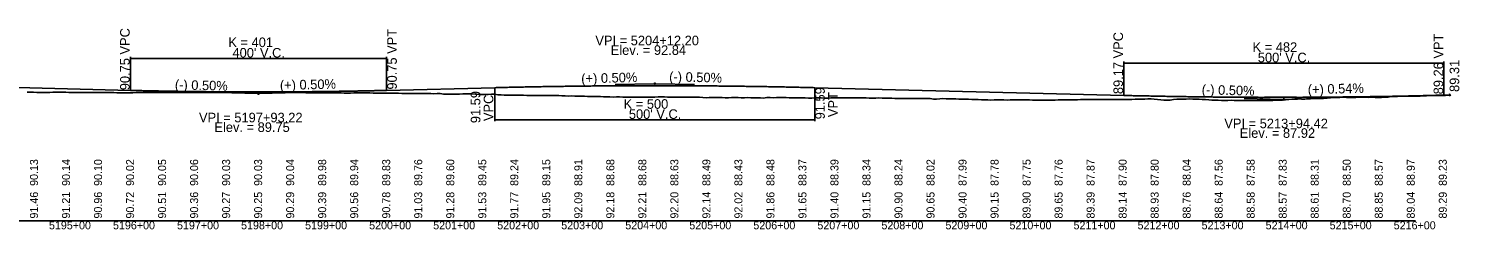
# Model space of a CAD drawing. Extents: x 2121671 to 2169879, y 557274 to 599957.
# Drawn here: x 2149002 to 2151237, y 576173 to 576487 of the extents above; entities that cross this region are included whole.
import ezdxf

# ---------------------------------------------------------------- set-up
doc = ezdxf.new("R2010")
doc.units = 0
for name, color, linetype in [('RD_DDB_GradeTX', 7, 'Continuous'), ('RD_DDB_Profile_EX', 7, 'Continuous'), ('RD_DDB_Profile_Lbl', 7, 'Continuous'), ('RD_DDB_Profile_PR', 7, 'Continuous'), ('RD_DDB_StaTX', 7, 'Continuous'), ('RD_DDB_StripGrade', 7, 'Continuous'), ('RD_DDB_VCLbl', 7, 'Continuous'), ('RD_GPK_Profile_Cell', 7, 'Continuous')]:
    doc.layers.add(name, color=color, linetype=linetype)

msp = doc.modelspace()

# ---------------------------------------------------------------- linework, layer by layer
at = {"layer": 'RD_DDB_GradeTX'}
for p, q in [((2149918.1, 576399.5), (2149979.1, 576401)), ((2150042.1, 576399.5), (2149981.1, 576401)), ((2149299.2, 576387.1), (2149360.1, 576385.6)), ((2149423.1, 576387.1), (2149362.1, 576385.6)), ((2150900.4, 576378), (2150961.3, 576376.5)), ((2151024.3, 576378.1), (2150963.3, 576376.5))]:
    msp.add_line(p, q, dxfattribs=at)
for centre in [(2149980.1, 576401), (2149361.1, 576385.6), (2150962.3, 576376.4), (2151221.5, 576383.4)]:
    msp.add_circle(centre, 1, dxfattribs=at)
at = {"layer": 'RD_DDB_Profile_EX'}
for points in [[(2149000.1, 576387.7), (2149005.1, 576387.7), (2149010.1, 576387.6), (2149015.1, 576387.5), (2149020.1, 576387.5), (2149025.1, 576387.5), (2149030.1, 576387.5), (2149035.1, 576387.5), (2149040.1, 576387.6), (2149045.1, 576387.6), (2149050.1, 576387.7), (2149055.1, 576387.6), (2149060.1, 576387.6), (2149065.1, 576387.5), (2149070.1, 576387.5), (2149075.1, 576387.5), (2149080.1, 576387.5), (2149085.1, 576387.4), (2149090.1, 576387.4), (2149095.1, 576387.4), (2149100.1, 576387.4), (2149105.1, 576387.4), (2149110.1, 576387.4), (2149115.1, 576387.3), (2149120.1, 576387.3), (2149125.1, 576387.3), (2149130.1, 576387.1), (2149135.1, 576387), (2149140.1, 576386.9), (2149145.1, 576386.8), (2149150.1, 576386.9), (2149155.1, 576386.9), (2149160.1, 576386.9), (2149165.1, 576386.9), (2149170.1, 576387), (2149175.1, 576387), (2149180.1, 576387), (2149185.1, 576387), (2149190.1, 576387), (2149195.1, 576387), (2149200.1, 576387), (2149205.1, 576387), (2149210.1, 576387), (2149215.1, 576387), (2149220.1, 576387.1), (2149225.1, 576387.1)], [(2149225.1, 576387.1), (2149230.1, 576387.2), (2149235.1, 576387.2), (2149240.1, 576387.3), (2149245.1, 576387.3), (2149250.1, 576387.2), (2149255.1, 576387.2), (2149260.1, 576387.2), (2149265.1, 576387.2), (2149270.1, 576387.1), (2149275.1, 576387.1), (2149280.1, 576387.1), (2149285.1, 576387.1), (2149290.1, 576387), (2149295.1, 576387), (2149300.1, 576387), (2149305.1, 576387), (2149310.1, 576387), (2149315.1, 576387), (2149320.1, 576387), (2149325.1, 576387), (2149330.1, 576387), (2149335.1, 576387), (2149340.1, 576387), (2149345.1, 576387), (2149350.1, 576387), (2149355.1, 576387), (2149360.1, 576387), (2149365.1, 576387), (2149370.1, 576387), (2149375.1, 576386.9), (2149380.1, 576386.9), (2149385.1, 576386.9), (2149390.1, 576386.9), (2149395.1, 576386.9), (2149400.1, 576387), (2149405.1, 576387), (2149410.1, 576387), (2149415.1, 576387.1), (2149420.1, 576387), (2149425.1, 576387), (2149430.1, 576387), (2149435.1, 576386.9), (2149440.1, 576386.8), (2149445.1, 576386.8), (2149450.1, 576386.7), (2149455.1, 576386.7), (2149460.1, 576386.7), (2149465.1, 576386.7), (2149470.1, 576386.8), (2149475.1, 576386.8), (2149480.1, 576386.6), (2149485.1, 576386.6), (2149490.1, 576386.5), (2149495.1, 576386.4), (2149500.1, 576386.4), (2149505.1, 576386.3), (2149510.1, 576386.5), (2149515.1, 576386.5), (2149520.1, 576386.5), (2149525.1, 576386.5), (2149530.1, 576386.5), (2149535.1, 576386.5), (2149540.1, 576386.4), (2149545.1, 576386.4), (2149550.1, 576386.3), (2149555.1, 576386.2), (2149560.1, 576386.1), (2149565.1, 576386), (2149570.1, 576386), (2149575.1, 576386), (2149580.1, 576386), (2149585.1, 576385.9), (2149590.1, 576385.9), (2149595.1, 576385.9), (2149600.1, 576385.8), (2149605.1, 576385.8), (2149610.1, 576385.8), (2149615.1, 576385.7), (2149620.1, 576385.6), (2149625.1, 576385.5), (2149630.1, 576385.5), (2149635.1, 576385.4), (2149640.1, 576385.5), (2149645.1, 576385.5), (2149650.1, 576384.9), (2149655.1, 576384.8), (2149660.1, 576384.8), (2149665.1, 576384.8), (2149670.1, 576384.8), (2149675.1, 576384.9), (2149680.1, 576385.2), (2149685.1, 576385.3), (2149690.1, 576385.2), (2149695.1, 576385.1), (2149700.1, 576384.9), (2149705.1, 576384.1), (2149710.1, 576384.1), (2149715.1, 576384), (2149720.1, 576384.1), (2149725.1, 576384.9)], [(2149725.1, 576384.9), (2149730.1, 576384.7), (2149735.1, 576383.7), (2149740.1, 576383.4), (2149745.1, 576383.3), (2149750.1, 576383.2), (2149755.1, 576383.1), (2149760.1, 576383.1), (2149765.1, 576383), (2149770.1, 576383), (2149775.1, 576382.9), (2149780.1, 576382.8), (2149785.1, 576382.7), (2149790.1, 576382.6), (2149795.1, 576382.5), (2149800.1, 576382.6), (2149805.1, 576382.6), (2149810.1, 576382.6), (2149815.1, 576382.6), (2149820.1, 576382.6), (2149825.1, 576382.6), (2149830.1, 576382.5), (2149835.1, 576382.1), (2149840.1, 576381.9), (2149845.1, 576381.6), (2149850.1, 576381.8), (2149855.1, 576381.6), (2149860.1, 576381.5), (2149865.1, 576381.4), (2149870.1, 576381.4), (2149875.1, 576381.1), (2149880.1, 576381), (2149885.1, 576381), (2149890.1, 576381.1), (2149895.1, 576381.1), (2149900.1, 576380.7), (2149905.1, 576380.4), (2149910.1, 576380.3), (2149915.1, 576380.1), (2149920.1, 576380.3), (2149925.1, 576380.3), (2149930.1, 576380), (2149935.1, 576379.7), (2149940.1, 576379.8), (2149945.1, 576379.9), (2149950.1, 576379.9), (2149955.1, 576379.9), (2149960.1, 576380.1), (2149965.1, 576380.2), (2149970.1, 576380.2), (2149975.1, 576380.1), (2149980.1, 576380.2), (2149985.1, 576380.3), (2149990.1, 576380.4), (2149995.1, 576380.3), (2150000.1, 576380.2), (2150005.1, 576380.2), (2150010.1, 576380.2), (2150015.1, 576380.1), (2150020.1, 576379.9), (2150025.1, 576379.8), (2150030.1, 576379.7), (2150035.1, 576379.8), (2150040.1, 576379.9), (2150045.1, 576379.9), (2150050.1, 576379.8), (2150055.1, 576379.3), (2150060.1, 576379.1), (2150065.1, 576379.2), (2150070.1, 576379.4), (2150075.1, 576379.4), (2150080.1, 576379.3), (2150085.1, 576379.2), (2150090.1, 576379), (2150095.1, 576379.1), (2150100.1, 576379.3), (2150105.1, 576379.3), (2150110.1, 576379.2), (2150115.1, 576378.9), (2150120.1, 576379), (2150125.1, 576379.2), (2150130.1, 576379), (2150135.1, 576378.8), (2150140.1, 576379), (2150145.1, 576378.7), (2150150.1, 576378.6), (2150155.1, 576379.3), (2150160.1, 576379.4), (2150165.1, 576379.1), (2150170.1, 576379.3), (2150175.1, 576379.3), (2150180.1, 576379.4), (2150185.1, 576379.4), (2150190.1, 576378.9), (2150195.1, 576378.7), (2150200.1, 576378.8), (2150205.1, 576378.9), (2150210.1, 576378.9), (2150215.1, 576378.7), (2150220.1, 576378.6), (2150225.1, 576378.5)], [(2150225.1, 576378.5), (2150230.1, 576378.9), (2150235.1, 576378.8), (2150240.1, 576378.9), (2150245.1, 576378.6), (2150250.1, 576378.6), (2150255.1, 576378.8), (2150260.1, 576378.7), (2150265.1, 576378.7), (2150270.1, 576378.8), (2150275.1, 576379), (2150280.1, 576378.8), (2150285.1, 576378.7), (2150290.1, 576378.7), (2150295.1, 576378.8), (2150300.1, 576378.8), (2150305.1, 576378.8), (2150310.1, 576378.7), (2150315.1, 576378.4), (2150320.1, 576378.6), (2150325.1, 576378.4), (2150330.1, 576378.7), (2150335.1, 576378.6), (2150340.1, 576378.6), (2150345.1, 576378.6), (2150350.1, 576378.3), (2150355.1, 576377.9), (2150360.1, 576378), (2150365.1, 576377.9), (2150370.1, 576378.1), (2150375.1, 576377.9), (2150380.1, 576378), (2150385.1, 576378.1), (2150390.1, 576378), (2150395.1, 576378), (2150400.1, 576377.8), (2150405.1, 576377.9), (2150410.1, 576377.9), (2150415.1, 576376.9), (2150420.1, 576376.9), (2150425.1, 576377.6), (2150430.1, 576377.7), (2150435.1, 576377.6), (2150440.1, 576377.5), (2150445.1, 576377.5), (2150450.1, 576377.3), (2150455.1, 576377), (2150460.1, 576377), (2150465.1, 576376.9), (2150470.1, 576376.7), (2150475.1, 576376.4), (2150480.1, 576376.2), (2150485.1, 576376.1), (2150490.1, 576376), (2150495.1, 576375.9), (2150500.1, 576375.7), (2150505.1, 576375.5), (2150510.1, 576375.7), (2150515.1, 576375.7), (2150520.1, 576375.7), (2150525.1, 576375.6), (2150530.1, 576375.5), (2150535.1, 576375.7), (2150540.1, 576375.9), (2150545.1, 576376), (2150550.1, 576375.9), (2150555.1, 576375.8), (2150560.1, 576375.7), (2150565.1, 576375.6), (2150570.1, 576375.5), (2150575.1, 576375.5), (2150580.1, 576375.5), (2150585.1, 576375.5), (2150590.1, 576375.5), (2150595.1, 576375.5), (2150600.1, 576375.5), (2150605.1, 576375.5), (2150610.1, 576375.6), (2150615.1, 576375.6), (2150620.1, 576375.7), (2150625.1, 576375.7), (2150630.1, 576375.8), (2150635.1, 576375.9), (2150640.1, 576376), (2150645.1, 576376.1), (2150650.1, 576376.1), (2150655.1, 576376.3), (2150660.1, 576376.3), (2150665.1, 576376.2), (2150670.1, 576376.2), (2150675.1, 576376.1), (2150680.1, 576376.3), (2150685.1, 576376.3), (2150690.1, 576376.2), (2150695.1, 576376.3), (2150700.1, 576376.3), (2150705.1, 576376.3), (2150710.1, 576376.3), (2150715.1, 576376.3), (2150720.1, 576376.3), (2150725.1, 576376.3)], [(2150725.1, 576376.3), (2150730.1, 576376.6), (2150735.1, 576376.8), (2150740.1, 576376.8), (2150745.1, 576376.9), (2150750.1, 576377.1), (2150755.1, 576377.2), (2150760.1, 576376.9), (2150765.1, 576376.1), (2150770.1, 576375.6), (2150775.1, 576375.3), (2150780.1, 576375.1), (2150785.1, 576375.4), (2150790.1, 576376.1), (2150795.1, 576376.6), (2150800.1, 576376.9), (2150805.1, 576376.9), (2150810.1, 576377), (2150815.1, 576377.1), (2150820.1, 576376.9), (2150825.1, 576376.9), (2150830.1, 576376.9), (2150835.1, 576376.5), (2150840.1, 576376.1), (2150845.1, 576375.6), (2150850.1, 576375.3), (2150855.1, 576375.2), (2150860.1, 576375.1), (2150865.1, 576374.7), (2150870.1, 576374.6), (2150875.1, 576375), (2150880.1, 576375.3), (2150885.1, 576374.7), (2150890.1, 576374.6), (2150895.1, 576374.5), (2150900.1, 576374.6), (2150905.1, 576374.6), (2150910.1, 576374.7), (2150915.1, 576374.8), (2150920.1, 576374.7), (2150925.1, 576374.7), (2150930.1, 576374.7), (2150935.1, 576374.7), (2150940.1, 576374.9), (2150945.1, 576375), (2150950.1, 576375.1), (2150955.1, 576375.1), (2150960.1, 576375.4), (2150965.1, 576375.6), (2150970.1, 576376.2), (2150975.1, 576376.6), (2150980.1, 576377.5), (2150985.1, 576377.1), (2150990.1, 576376.7), (2150995.1, 576376.8), (2151000.1, 576377.7), (2151005.1, 576378), (2151010.1, 576378.2), (2151015.1, 576378.4), (2151020.1, 576378.4), (2151025.1, 576378.4), (2151030.1, 576378.6), (2151035.1, 576379.1), (2151040.1, 576379.5), (2151045.1, 576379.5), (2151050.1, 576379.4), (2151055.1, 576379.9), (2151060.1, 576379.4), (2151065.1, 576379.4), (2151070.1, 576379.3), (2151075.1, 576379.3), (2151080.1, 576379.8), (2151085.1, 576380), (2151090.1, 576380), (2151095.1, 576379.5), (2151100.1, 576380), (2151105.1, 576379.5), (2151110.1, 576379.6), (2151115.1, 576379.5), (2151120.1, 576379.8), (2151125.1, 576380.2), (2151130.1, 576380.8), (2151135.1, 576381.1), (2151140.1, 576381.2), (2151145.1, 576381.3), (2151150.1, 576381.3), (2151155.1, 576381.4), (2151160.1, 576381.6), (2151165.1, 576381.6), (2151170.1, 576381.7), (2151175.1, 576381.7), (2151180.1, 576382.1), (2151185.1, 576382.3), (2151190.1, 576382.6), (2151195.1, 576382.6), (2151200.1, 576382.5), (2151205.1, 576382.4), (2151210.1, 576382.6), (2151215.1, 576382.7), (2151220.1, 576383.2), (2151221.5, 576383.2)]]:
    msp.add_lwpolyline(points, dxfattribs=at)
at = {"layer": 'RD_DDB_Profile_PR'}
for p, q in [((2148964.4, 576395.5), (2149161.1, 576390.6)), ((2149561.1, 576390.6), (2149730.1, 576394.8)), ((2150230.1, 576394.8), (2150712.3, 576382.7)), ((2151212.3, 576383.1), (2151221.5, 576383.4))]:
    msp.add_line(p, q, dxfattribs=at)
for points in [[(2149730.1, 576394.8), (2149740.1, 576395), (2149750.1, 576395.3), (2149760.1, 576395.5), (2149770.1, 576395.7), (2149780.1, 576395.9), (2149790.1, 576396.1), (2149800.1, 576396.3), (2149810.1, 576396.5), (2149820.1, 576396.6), (2149830.1, 576396.8), (2149840.1, 576396.9), (2149850.1, 576397.1), (2149860.1, 576397.2), (2149870.1, 576397.3), (2149880.1, 576397.4), (2149890.1, 576397.5), (2149900.1, 576397.6), (2149910.1, 576397.7), (2149920.1, 576397.7), (2149930.1, 576397.8), (2149940.1, 576397.8), (2149950.1, 576397.9), (2149960.1, 576397.9), (2149970.1, 576397.9), (2149980.1, 576397.9), (2149990.1, 576397.9), (2150000.1, 576397.9), (2150010.1, 576397.9), (2150020.1, 576397.8), (2150030.1, 576397.8), (2150040.1, 576397.7), (2150050.1, 576397.7), (2150060.1, 576397.6), (2150070.1, 576397.5), (2150080.1, 576397.4), (2150090.1, 576397.3), (2150100.1, 576397.2), (2150110.1, 576397.1), (2150120.1, 576396.9), (2150130.1, 576396.8), (2150140.1, 576396.6), (2150150.1, 576396.5), (2150160.1, 576396.3), (2150170.1, 576396.1), (2150180.1, 576395.9), (2150190.1, 576395.7), (2150200.1, 576395.5), (2150210.1, 576395.2), (2150220.1, 576395), (2150230.1, 576394.8)], [(2149161.1, 576390.6), (2149169.1, 576390.4), (2149177.1, 576390.2), (2149185.1, 576390), (2149193.1, 576389.8), (2149201.1, 576389.7), (2149209.1, 576389.5), (2149217.1, 576389.4), (2149225.1, 576389.2), (2149233.1, 576389.1), (2149241.1, 576389), (2149249.1, 576388.9), (2149257.1, 576388.7), (2149265.1, 576388.6), (2149273.1, 576388.6), (2149281.1, 576388.5), (2149289.1, 576388.4), (2149297.1, 576388.3), (2149305.1, 576388.3), (2149313.1, 576388.2), (2149321.1, 576388.2), (2149329.1, 576388.1), (2149337.1, 576388.1), (2149345.1, 576388.1), (2149353.1, 576388.1), (2149361.1, 576388.1), (2149369.1, 576388.1), (2149377.1, 576388.1), (2149385.1, 576388.1), (2149393.1, 576388.1), (2149401.1, 576388.2), (2149409.1, 576388.2), (2149417.1, 576388.3), (2149425.1, 576388.3), (2149433.1, 576388.4), (2149441.1, 576388.5), (2149449.1, 576388.6), (2149457.1, 576388.6), (2149465.1, 576388.7), (2149473.1, 576388.9), (2149481.1, 576389), (2149489.1, 576389.1), (2149497.1, 576389.2), (2149505.1, 576389.4), (2149513.1, 576389.5), (2149521.1, 576389.7), (2149529.1, 576389.8), (2149537.1, 576390), (2149545.1, 576390.2), (2149553.1, 576390.4), (2149561.1, 576390.6)], [(2150712.3, 576382.7), (2150722.3, 576382.4), (2150732.3, 576382.2), (2150742.3, 576382), (2150752.3, 576381.8), (2150762.3, 576381.6), (2150772.3, 576381.4), (2150782.3, 576381.2), (2150792.3, 576381), (2150802.3, 576380.9), (2150812.3, 576380.7), (2150822.3, 576380.6), (2150832.3, 576380.4), (2150842.3, 576380.3), (2150852.3, 576380.2), (2150862.3, 576380.1), (2150872.3, 576380), (2150882.3, 576379.9), (2150892.3, 576379.9), (2150902.3, 576379.8), (2150912.3, 576379.8), (2150922.3, 576379.7), (2150932.3, 576379.7), (2150942.3, 576379.7), (2150952.3, 576379.7), (2150962.3, 576379.7), (2150972.3, 576379.7), (2150982.3, 576379.7), (2150992.3, 576379.7), (2151002.3, 576379.8), (2151012.3, 576379.8), (2151022.3, 576379.9), (2151032.3, 576380), (2151042.3, 576380.1), (2151052.3, 576380.2), (2151062.3, 576380.3), (2151072.3, 576380.4), (2151082.3, 576380.5), (2151092.3, 576380.7), (2151102.3, 576380.8), (2151112.3, 576381), (2151122.3, 576381.1), (2151132.3, 576381.3), (2151142.3, 576381.5), (2151152.3, 576381.7), (2151162.3, 576381.9), (2151172.3, 576382.1), (2151182.3, 576382.4), (2151192.3, 576382.6), (2151202.3, 576382.9), (2151212.3, 576383.1)]]:
    msp.add_spline(points, degree=3, dxfattribs=at)
at = {"layer": 'RD_DDB_VCLbl'}
for p, q in [((2149161.1, 576443.1), (2149161.1, 576390.6)), ((2149161.1, 576440.6), (2149561.1, 576440.6)), ((2149561.1, 576443.1), (2149561.1, 576390.6)), ((2150712.3, 576435.6), (2150712.3, 576382.7)), ((2150712.3, 576433.1), (2151212.3, 576433.1)), ((2151212.3, 576435.6), (2151212.3, 576383.1)), ((2149730.1, 576342.3), (2149730.1, 576394.8)), ((2150230.1, 576342.3), (2150230.1, 576394.8)), ((2149730.1, 576344.8), (2150230.1, 576344.8))]:
    msp.add_line(p, q, dxfattribs=at)
at = {"layer": 'RD_GPK_Profile_Cell'}
msp.add_line((2146667.9, 576186.8), (2151167.9, 576186.8), dxfattribs=at)

# ---------------------------------------------------------------- texts
at = {"layer": 'RD_DDB_GradeTX'}
for s, rotation, p in [('(+) 0.50%', 1.4298, (2149865.4, 576401.5)), ('(-) 0.50%', 358.5653, (2150002.4, 576404.7)), ('(-) 0.50%', 358.5698, (2149230.5, 576392.1)), ('(+) 0.50%', 1.4298, (2149394.8, 576391.1)), ('(-) 0.50%', 358.5653, (2150834, 576384.4)), ('(+) 0.54%', 1.5363, (2151000, 576384.4))]:
    msp.add_text(s, height=15, rotation=rotation, dxfattribs=at).set_placement(p)
at = {"layer": 'RD_DDB_Profile_Lbl'}
for s, p in [('VPI = 5204+12.20', (2149887.3, 576461)), ('Elev. = 92.84', (2149911.3, 576446)), ('VPI = 5197+93.22', (2149268.3, 576340.6)), ('Elev. = 89.75', (2149292.4, 576325.6)), ('VPI = 5213+94.42', (2150869.5, 576331.4)), ('Elev. = 87.92', (2150893.6, 576316.4))]:
    msp.add_text(s, height=15, dxfattribs=at).set_placement(p)
msp.add_text('89.31', height=15, rotation=90, dxfattribs=at).set_placement((2151236.3, 576388.1))
at = {"layer": 'RD_DDB_StaTX'}
for s, p in [('5195+00', (2149034, 576173.5)), ('5196+00', (2149134, 576173.5)), ('5197+00', (2149234, 576173.5)), ('5198+00', (2149334, 576173.5)), ('5199+00', (2149434, 576173.5)), ('5200+00', (2149534, 576173.5)), ('5201+00', (2149634, 576173.5)), ('5202+00', (2149734, 576173.5)), ('5203+00', (2149834, 576173.5)), ('5204+00', (2149934, 576173.5)), ('5205+00', (2150034, 576173.5)), ('5206+00', (2150134, 576173.5)), ('5207+00', (2150234, 576173.5)), ('5208+00', (2150334, 576173.5)), ('5209+00', (2150434, 576173.5)), ('5210+00', (2150534, 576173.5)), ('5211+00', (2150634, 576173.5)), ('5212+00', (2150734, 576173.5)), ('5213+00', (2150834, 576173.5)), ('5214+00', (2150934, 576173.5)), ('5215+00', (2151034, 576173.5)), ('5216+00', (2151134, 576173.5))]:
    msp.add_text(s, height=12.5, dxfattribs=at).set_placement(p)
at = {"layer": 'RD_DDB_StripGrade'}
for s, height, p in [('90.75 VPC', 15, (2149160.1, 576390.8)), ('90.75 VPT', 15, (2149577.2, 576391.8)), ('89.17 VPC', 15, (2150711.3, 576384.7)), ('89.26 VPT', 15, (2151211.3, 576384.4)), ('91.59 ', 15, (2150245.6, 576345.3)), ('91.59 ', 15, (2149707.7, 576339.3)), ('VPC', 15, (2149727.9, 576342.6)), ('VPT', 15, (2150265.8, 576348.8)), ('90.13', 12.5, (2149016.9, 576241.3)), ('90.14', 12.5, (2149066.9, 576241.3)), ('90.10', 12.5, (2149116.9, 576241.3)), ('90.02', 12.5, (2149166.9, 576241.3)), ('90.05', 12.5, (2149216.9, 576241.3)), ('90.06', 12.5, (2149266.9, 576241.3)), ('90.03', 12.5, (2149316.9, 576241.3)), ('90.03', 12.5, (2149366.9, 576241.3)), ('90.04', 12.5, (2149416.9, 576241.3)), ('89.98', 12.5, (2149466.9, 576241.3)), ('89.94', 12.5, (2149516.9, 576241.3)), ('89.83', 12.5, (2149566.9, 576241.3)), ('89.76', 12.5, (2149616.9, 576241.3)), ('89.60', 12.5, (2149666.9, 576241.3)), ('89.45', 12.5, (2149716.9, 576241.3)), ('89.24', 12.5, (2149766.9, 576241.3)), ('89.15', 12.5, (2149816.9, 576241.3)), ('88.91', 12.5, (2149866.9, 576241.3)), ('88.68', 12.5, (2149916.9, 576241.3)), ('88.68', 12.5, (2149966.9, 576241.3)), ('88.63', 12.5, (2150016.9, 576241.3)), ('88.49', 12.5, (2150066.9, 576241.3)), ('88.43', 12.5, (2150116.9, 576241.3)), ('88.48', 12.5, (2150166.9, 576241.3)), ('88.37', 12.5, (2150216.9, 576241.3)), ('88.39', 12.5, (2150266.9, 576241.3)), ('88.34', 12.5, (2150316.9, 576241.3)), ('88.24', 12.5, (2150366.9, 576241.3)), ('88.02', 12.5, (2150416.9, 576241.3)), ('87.99', 12.5, (2150466.9, 576241.3)), ('87.78', 12.5, (2150516.9, 576241.3)), ('87.75', 12.5, (2150566.9, 576241.3)), ('87.76', 12.5, (2150616.9, 576241.3)), ('87.87', 12.5, (2150666.9, 576241.3)), ('87.90', 12.5, (2150716.9, 576241.3)), ('87.80', 12.5, (2150766.9, 576241.3)), ('88.04', 12.5, (2150816.9, 576241.3)), ('87.56', 12.5, (2150866.9, 576241.3)), ('87.58', 12.5, (2150916.9, 576241.3)), ('87.83', 12.5, (2150966.9, 576241.3)), ('88.31', 12.5, (2151016.9, 576241.3)), ('88.50', 12.5, (2151066.9, 576241.3)), ('88.57', 12.5, (2151116.9, 576241.3)), ('88.97', 12.5, (2151166.9, 576241.3)), ('89.23', 12.5, (2151216.9, 576241.3)), ('91.46', 12.5, (2149016.9, 576190.3)), ('91.21', 12.5, (2149066.9, 576190.3)), ('90.96', 12.5, (2149116.9, 576190.3)), ('90.72', 12.5, (2149166.9, 576190.3)), ('90.51', 12.5, (2149216.9, 576190.3)), ('90.36', 12.5, (2149266.9, 576190.3)), ('90.27', 12.5, (2149316.9, 576190.3)), ('90.25', 12.5, (2149366.9, 576190.3)), ('90.29', 12.5, (2149416.9, 576190.3)), ('90.39', 12.5, (2149466.9, 576190.3)), ('90.56', 12.5, (2149516.9, 576190.3)), ('90.78', 12.5, (2149566.9, 576190.3)), ('91.03', 12.5, (2149616.9, 576190.3)), ('91.28', 12.5, (2149666.9, 576190.3)), ('91.53', 12.5, (2149716.9, 576190.3)), ('91.77', 12.5, (2149766.9, 576190.3)), ('91.95', 12.5, (2149816.9, 576190.3)), ('92.09', 12.5, (2149866.9, 576190.3)), ('92.18', 12.5, (2149916.9, 576190.3)), ('92.21', 12.5, (2149966.9, 576190.3)), ('92.20', 12.5, (2150016.9, 576190.3)), ('92.14', 12.5, (2150066.9, 576190.3)), ('92.02', 12.5, (2150116.9, 576190.3)), ('91.86', 12.5, (2150166.9, 576190.3)), ('91.65', 12.5, (2150216.9, 576190.3)), ('91.40', 12.5, (2150266.9, 576190.3)), ('91.15', 12.5, (2150316.9, 576190.3)), ('90.90', 12.5, (2150366.9, 576190.3)), ('90.65', 12.5, (2150416.9, 576190.3)), ('90.40', 12.5, (2150466.9, 576190.3)), ('90.15', 12.5, (2150516.9, 576190.3)), ('89.90', 12.5, (2150566.9, 576190.3)), ('89.65', 12.5, (2150616.9, 576190.3)), ('89.39', 12.5, (2150666.9, 576190.3)), ('89.14', 12.5, (2150716.9, 576190.3)), ('88.93', 12.5, (2150766.9, 576190.3)), ('88.76', 12.5, (2150816.9, 576190.3)), ('88.64', 12.5, (2150866.9, 576190.3)), ('88.58', 12.5, (2150916.9, 576190.3)), ('88.57', 12.5, (2150966.9, 576190.3)), ('88.61', 12.5, (2151016.9, 576190.3)), ('88.70', 12.5, (2151066.9, 576190.3)), ('88.85', 12.5, (2151116.9, 576190.3)), ('89.04', 12.5, (2151166.9, 576190.3)), ('89.29', 12.5, (2151216.9, 576190.3))]:
    msp.add_text(s, height=height, rotation=90, dxfattribs=at).set_placement(p)
at = {"layer": 'RD_DDB_VCLbl'}
for s, p in [('K = 401', (2149314.2, 576458.2)), ('K = 482', (2150913.6, 576450.7)), ("400' V.C.", (2149320.6, 576441.8)), ("500' V.C.", (2150921.8, 576434.4)), ('K = 500', (2149931.4, 576361.8)), ("500' V.C.", (2149939.6, 576346))]:
    msp.add_text(s, height=15, dxfattribs=at).set_placement(p)

doc.saveas('drawing.dxf')
